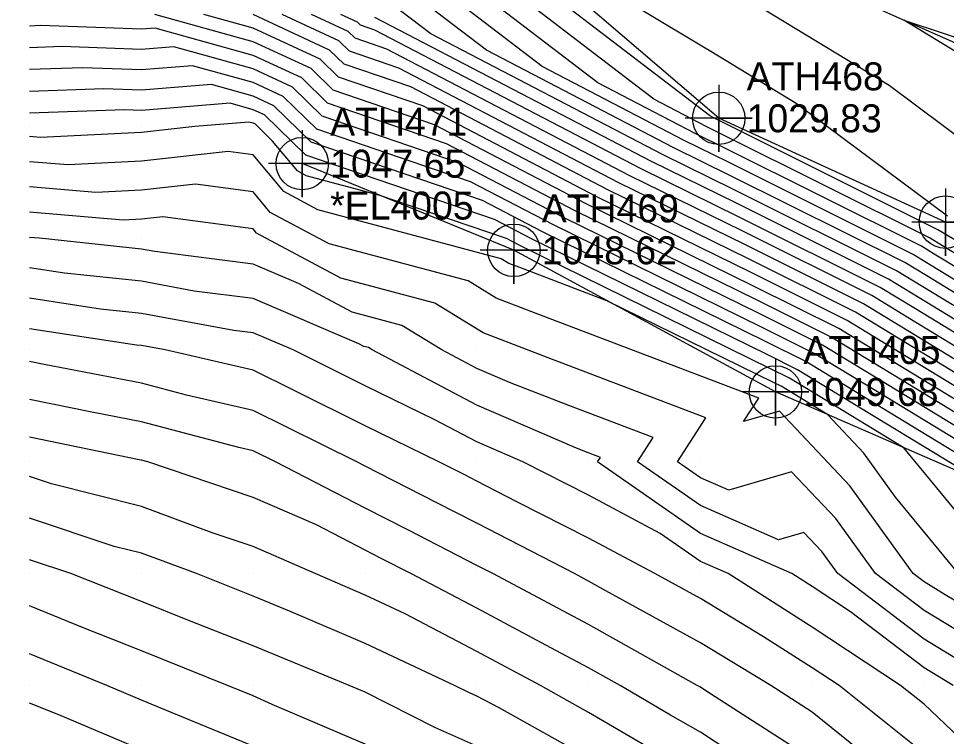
# Model space of a CAD drawing. Extents: x 1213164 to 1213550, y 766120 to 766870.
# Drawn here: x 1213169 to 1213252, y 766335.4 to 766399.6 of the extents above; entities that cross this region are included whole.
import ezdxf

# ---------------------------------------------------------------- set-up
doc = ezdxf.new("R2010")
doc.units = 0
for name, color, linetype in [('Default', 7, 'Continuous'), ('Exist DTM Breakline', 7, 'Continuous'), ('Exist DTM Breakline Cogo Comment', 7, 'Continuous'), ('Exist DTM Breakline Cogo Elevation', 7, 'Continuous'), ('Exist DTM Breakline Cogo Number', 7, 'Continuous'), ('Exist DTM Breakline Cogo Point CELL', 7, 'Continuous'), ('Exist DTM QL2 LIDAR Elevation Point', 7, 'Continuous'), ('Exist Roads EOP', 7, 'Continuous')]:
    doc.layers.add(name, color=color, linetype=linetype)

msp = doc.modelspace()

# ---------------------------------------------------------------- linework, layer by layer
at = {"layer": 'Default'}
for points in [[(1213252.099, 766381.968), (1213238.569, 766392.051), (1213230.917, 766396.699), (1213230.271, 766397.092), (1213210.05, 766409.212)], [(1213302.597, 766358.408), (1213282.153, 766375.636), (1213280.103, 766377.363), (1213253.141, 766379.599), (1213251.598, 766380.538), (1213251.233, 766380.76), (1213231.678, 766390.516), (1213231.474, 766390.617), (1213230.808, 766390.964), (1213207.579, 766408.748)], [(1213300.518, 766357.868), (1213281.492, 766373.902), (1213279.584, 766375.509), (1213254.492, 766377.59), (1213251.259, 766379.558), (1213250.495, 766380.022), (1213231.934, 766389.283), (1213230.499, 766389.988), (1213225.821, 766392.426), (1213206.352, 766407.332)], [(1213304.578, 766352.413), (1213298.807, 766356.947), (1213298.439, 766357.329), (1213280.831, 766372.168), (1213279.065, 766373.656), (1213255.843, 766375.581), (1213250.92, 766378.578), (1213249.758, 766379.285), (1213232.19, 766388.05), (1213229.523, 766389.36), (1213220.835, 766393.889), (1213205.126, 766405.916)], [(1213304.23, 766350.488), (1213296.832, 766356.3), (1213296.361, 766356.79), (1213280.17, 766370.434), (1213278.547, 766371.802), (1213257.194, 766373.572), (1213250.581, 766377.597), (1213249.02, 766378.548), (1213232.445, 766386.817), (1213228.548, 766388.731), (1213215.848, 766395.352), (1213203.899, 766404.5)], [(1213248.618, 766403.962), (1213263.002, 766397.56), (1213276.559, 766386.527), (1213281.848, 766382.566), (1213283.669, 766380.515), (1213285.825, 766378.11), (1213289.231, 766374.252), (1213283.474, 766379.104), (1213281.14, 766381.071), (1213276.351, 766381.468), (1213254.307, 766388.113), (1213246.883, 766393.646), (1213230.055, 766403.868)], [(1213303.882, 766348.563), (1213294.857, 766355.653), (1213294.282, 766356.251), (1213279.509, 766368.7), (1213278.028, 766369.948), (1213258.545, 766371.563), (1213250.242, 766376.617), (1213248.282, 766377.811), (1213232.701, 766385.584), (1213227.572, 766388.103), (1213210.861, 766396.814), (1213202.672, 766403.084)], [(1213303.534, 766346.638), (1213292.883, 766355.006), (1213292.204, 766355.711), (1213278.849, 766366.966), (1213277.51, 766368.094), (1213259.896, 766369.555), (1213249.903, 766375.637), (1213247.544, 766377.073), (1213232.957, 766384.351), (1213226.597, 766387.474), (1213205.874, 766398.277), (1213201.445, 766401.668)], [(1213305.353, 766325.548), (1213297.859, 766333.832), (1213287.001, 766344.237), (1213279.059, 766350.477), (1213277.654, 766351.936), (1213274.223, 766354.827), (1213273.879, 766355.117), (1213269.354, 766355.492), (1213247.531, 766368.776), (1213242.379, 766371.912), (1213234.746, 766375.72), (1213219.769, 766383.075), (1213206.226, 766390.135), (1213197.148, 766393.231), (1213195.169, 766395.169), (1213190, 766397.563), (1213181.204, 766400)], [(1213299.261, 766335.539), (1213291.938, 766342.557), (1213281.033, 766351.124), (1213279.733, 766352.475), (1213274.884, 766356.561), (1213274.398, 766356.971), (1213268.003, 766357.501), (1213247.87, 766369.756), (1213243.117, 766372.649), (1213234.49, 766376.953), (1213220.745, 766383.704), (1213205.157, 766391.829), (1213197.638, 766394.394), (1213195.999, 766395.999), (1213190, 766398.778), (1213185.588, 766400)], [(1213300.664, 766337.246), (1213296.875, 766340.877), (1213283.008, 766351.771), (1213281.811, 766353.015), (1213275.545, 766358.295), (1213274.916, 766358.825), (1213266.652, 766359.51), (1213248.209, 766370.736), (1213243.855, 766373.387), (1213234.235, 766378.186), (1213221.72, 766384.332), (1213204.087, 766393.524), (1213198.128, 766395.556), (1213196.828, 766396.828), (1213190, 766399.992)], [(1213301.812, 766339.197), (1213284.983, 766352.418), (1213283.89, 766353.554), (1213276.205, 766360.029), (1213275.435, 766360.679), (1213265.301, 766361.519), (1213248.548, 766371.716), (1213244.593, 766374.124), (1213233.979, 766379.419), (1213222.695, 766384.961), (1213203.018, 766395.218), (1213198.618, 766396.719), (1213197.658, 766397.658), (1213192.603, 766400)], [(1213302.49, 766340.863), (1213286.958, 766353.065), (1213285.968, 766354.093), (1213276.866, 766361.763), (1213275.954, 766362.533), (1213263.95, 766363.528), (1213248.887, 766372.697), (1213245.33, 766374.861), (1213233.723, 766380.652), (1213223.671, 766385.589), (1213201.949, 766396.913), (1213199.107, 766397.882), (1213198.488, 766398.488), (1213195.224, 766400)], [(1213302.838, 766342.788), (1213288.933, 766353.712), (1213288.047, 766354.633), (1213277.527, 766363.498), (1213276.472, 766364.386), (1213262.599, 766365.537), (1213249.226, 766373.677), (1213246.068, 766375.599), (1213233.468, 766381.885), (1213224.646, 766386.218), (1213200.879, 766398.607), (1213199.597, 766399.044), (1213199.318, 766399.318), (1213197.845, 766400)], [(1213303.186, 766344.713), (1213290.908, 766354.359), (1213290.125, 766355.172), (1213278.188, 766365.232), (1213276.991, 766366.24), (1213261.247, 766367.546), (1213249.565, 766374.657), (1213246.806, 766376.336), (1213233.212, 766383.118), (1213225.622, 766386.846), (1213200.887, 766399.74)], [(1213248.178, 766399.505), (1213255.505, 766397.074), (1213258.06, 766395.937), (1213262.243, 766392.532), (1213256.515, 766394.259), (1213255.196, 766395.241), (1213248.178, 766399.505)], [(1213302.744, 766325.175), (1213296.457, 766332.125), (1213282.064, 766345.917), (1213277.084, 766349.83), (1213275.576, 766351.397), (1213273.562, 766353.093), (1213273.36, 766353.263), (1213270.705, 766353.484), (1213247.193, 766367.796), (1213241.641, 766371.175), (1213235.002, 766374.487), (1213218.794, 766382.447), (1213207.296, 766388.441), (1213196.658, 766392.069), (1213194.339, 766394.339), (1213190, 766396.349), (1213181.218, 766398.782), (1213180, 766398.685), (1213170.991, 766399.009), (1213170, 766398.972)], [(1213300.135, 766324.802), (1213295.055, 766330.418), (1213277.127, 766347.598), (1213275.109, 766349.183), (1213273.497, 766350.858), (1213272.902, 766351.359), (1213272.842, 766351.41), (1213272.057, 766351.475), (1213246.854, 766366.815), (1213240.903, 766370.437), (1213235.257, 766373.254), (1213217.818, 766381.818), (1213208.365, 766386.746), (1213196.168, 766390.906), (1213193.509, 766393.509), (1213190, 766395.135), (1213182.897, 766397.103), (1213180, 766396.872), (1213172.872, 766397.128), (1213170, 766397.021)], [(1213303.716, 766317.22), (1213297.526, 766324.429), (1213293.652, 766328.711), (1213275.153, 766346.438), (1213274.173, 766347.51), (1213273.467, 766348.054), (1213272.271, 766349.201), (1213271.551, 766349.728), (1213270.143, 766350.562), (1213268.666, 766352.352), (1213246.515, 766365.835), (1213240.165, 766369.7), (1213235.513, 766372.021), (1213216.843, 766381.19), (1213209.435, 766385.052), (1213195.678, 766389.743), (1213192.68, 766392.68), (1213190, 766393.921), (1213184.577, 766395.423), (1213180, 766395.058), (1213174.753, 766395.247), (1213170, 766395.07)], [(1213302.619, 766315.088), (1213294.917, 766324.056), (1213292.25, 766327.004), (1213279.514, 766339.209), (1213275.46, 766343.643), (1213272.538, 766345.896), (1213271.662, 766346.735), (1213269.701, 766348.17), (1213265.866, 766350.443), (1213261.842, 766355.319), (1213246.176, 766364.855), (1213239.428, 766368.963), (1213235.769, 766370.788), (1213215.868, 766380.561), (1213210.504, 766383.357), (1213195.188, 766388.581), (1213191.85, 766391.85), (1213190, 766392.707), (1213186.256, 766393.744), (1213180, 766393.245), (1213176.634, 766393.366), (1213170, 766393.119)], [(1213301.521, 766312.955), (1213292.308, 766323.683), (1213290.848, 766325.297), (1213283.875, 766331.98), (1213276.747, 766339.777), (1213271.609, 766343.737), (1213271.054, 766344.269), (1213267.852, 766346.612), (1213261.588, 766350.323), (1213255.019, 766358.286), (1213245.837, 766363.875), (1213238.69, 766368.225), (1213236.024, 766369.555), (1213214.892, 766379.933), (1213211.573, 766381.663), (1213194.698, 766387.418), (1213191.02, 766391.02), (1213190, 766391.492), (1213187.936, 766392.064), (1213180, 766391.432), (1213178.515, 766391.485), (1213170, 766391.167)], [(1213257.311, 766350.204), (1213248.195, 766361.253), (1213245.498, 766362.895), (1213237.952, 766367.488), (1213236.28, 766368.322), (1213213.917, 766379.305), (1213212.643, 766379.969), (1213201.24, 766383.857), (1213194.746, 766385.586), (1213193.951, 766386.012), (1213191.722, 766388.69), (1213190.19, 766390.19), (1213190, 766390.278), (1213189.615, 766390.385), (1213184.785, 766390), (1213180, 766389.457), (1213170.989, 766389.011), (1213170, 766389.094)], [(1213253.033, 766350.085), (1213247.455, 766356.846), (1213244.623, 766360.776), (1213241.371, 766364.22), (1213237.214, 766366.751), (1213236.535, 766367.089), (1213221.632, 766374.408), (1213213.857, 766377.364), (1213212.875, 766377.744), (1213212.189, 766378.163), (1213195.776, 766382.533), (1213192.735, 766384.161), (1213190, 766387.447), (1213187.753, 766387.753), (1213180, 766386.872), (1213173.452, 766386.548), (1213170, 766386.839)], [(1213262.303, 766341.939), (1213251.894, 766348.106), (1213250, 766349.256), (1213249.021, 766350), (1213243.367, 766357.847), (1213237.058, 766364.528), (1213233.859, 766363.593), (1213235.215, 766365.688), (1213215.311, 766373.254), (1213211.724, 766374.643), (1213209.22, 766376.174), (1213196.805, 766379.479), (1213191.518, 766382.31), (1213190, 766384.134), (1213184.837, 766384.837), (1213180, 766384.288), (1213175.914, 766384.086), (1213170, 766384.584)], [(1213258.406, 766341.594), (1213250, 766346.698), (1213245.654, 766350), (1213242.11, 766354.919), (1213238.156, 766359.106), (1213232.537, 766357.463), (1213230, 766358.575), (1213227.959, 766360), (1213230.497, 766363.924), (1213216.765, 766369.145), (1213210.573, 766371.542), (1213206.25, 766374.186), (1213197.834, 766376.426), (1213190.302, 766380.459), (1213190, 766380.821), (1213181.922, 766381.922), (1213180, 766381.704), (1213178.377, 766381.623), (1213170, 766382.329)], [(1213256.819, 766340), (1213250, 766344.141), (1213242.287, 766350), (1213240.854, 766351.99), (1213239.254, 766353.684), (1213236.981, 766353.019), (1213230, 766356.079), (1213224.382, 766360), (1213225.78, 766362.161), (1213218.219, 766365.035), (1213212.909, 766367.091), (1213210, 766368.348), (1213206.872, 766370), (1213203.28, 766372.197), (1213198.863, 766373.372), (1213194.051, 766375.949), (1213190, 766377.684), (1213181.202, 766378.798), (1213180, 766379.02), (1213170.871, 766380), (1213170, 766380.073)], [(1213252.608, 766340), (1213250, 766341.583), (1213243.412, 766346.588), (1213240, 766348.837), (1213238.174, 766350), (1213230, 766353.582), (1213220.806, 766360), (1213221.063, 766360.397), (1213219.672, 766360.926), (1213218.696, 766361.304), (1213210, 766365.062), (1213200.65, 766370), (1213200.31, 766370.208), (1213199.892, 766370.319), (1213199.437, 766370.563), (1213190, 766374.604), (1213184.728, 766375.272), (1213180, 766376.143), (1213173.118, 766376.882), (1213170, 766377.356)], [(1213288.488, 766300), (1213280, 766308.773), (1213278.784, 766310), (1213270, 766319.601), (1213269.614, 766320), (1213260, 766328.926), (1213258.753, 766330), (1213250, 766338.319), (1213247.903, 766340), (1213240, 766345.208), (1213232.477, 766350), (1213230, 766351.086), (1213226.405, 766353.595), (1213220, 766357.02), (1213214.108, 766360), (1213210, 766361.775), (1213206.237, 766363.763), (1213200, 766366.795), (1213193.559, 766370), (1213190, 766371.524), (1213188.255, 766371.745), (1213180, 766373.266), (1213176.341, 766373.659), (1213170, 766374.624)], [(1213254.11, 766330), (1213250, 766333.906), (1213242.397, 766340), (1213240, 766341.58), (1213235.649, 766344.351), (1213230, 766347.761), (1213225.936, 766350), (1213220, 766353.174), (1213213.578, 766356.422), (1213210, 766358.269), (1213208.856, 766358.856), (1213206.616, 766360), (1213200, 766363.217), (1213193.598, 766366.402), (1213190, 766368.183), (1213182.11, 766370), (1213180, 766370.389), (1213179.565, 766370.435), (1213170, 766371.892)], [(1213280, 766300.545), (1213270.63, 766310), (1213270, 766310.688), (1213260.995, 766320), (1213260, 766320.923), (1213253.326, 766326.674), (1213250, 766329.544), (1213249.402, 766330), (1213240, 766337.619), (1213236.293, 766340), (1213230, 766343.799), (1213221.541, 766348.459), (1213220, 766349.323), (1213218.726, 766350), (1213210, 766354.505), (1213206.367, 766356.367), (1213200, 766359.619), (1213199.265, 766360), (1213190, 766364.587), (1213184.041, 766365.959), (1213180, 766367.027), (1213171.308, 766368.692), (1213170, 766368.959)], [(1213276.631, 766300), (1213270, 766306.688), (1213266.673, 766310), (1213260, 766316.88), (1213256.467, 766320), (1213250, 766325.581), (1213244.199, 766330), (1213240, 766333.403), (1213230.486, 766339.514), (1213230, 766339.835), (1213229.895, 766339.895), (1213229.716, 766340), (1213220, 766345.451), (1213211.434, 766350), (1213210, 766350.74), (1213203.878, 766353.878), (1213200, 766355.859), (1213191.999, 766360), (1213190, 766360.99), (1213188.714, 766361.286), (1213180, 766363.589), (1213175.561, 766364.439), (1213170, 766365.577)], [(1213270, 766302.77), (1213262.739, 766310), (1213260, 766312.824), (1213251.874, 766320), (1213250, 766321.617), (1213243.209, 766326.791), (1213240, 766329.186), (1213238.829, 766330), (1213230, 766335.826), (1213227.335, 766337.335), (1213222.813, 766340), (1213220, 766341.578), (1213216.634, 766343.366), (1213210, 766346.896), (1213204.099, 766350), (1213201.389, 766351.389), (1213200, 766352.098), (1213195.651, 766354.349), (1213190, 766356.816), (1213180.571, 766360), (1213180, 766360.151), (1213179.813, 766360.187), (1213170, 766362.194)], [(1213268.891, 766300), (1213260, 766308.854), (1213258.598, 766310), (1213250, 766317.59), (1213246.649, 766320), (1213240, 766324.962), (1213232.752, 766330), (1213230, 766331.816), (1213224.775, 766334.775), (1213220, 766337.59), (1213215.698, 766340), (1213210, 766343.032), (1213203.604, 766346.396), (1213200, 766348.087), (1213195.55, 766350), (1213190, 766352.422), (1213186.342, 766353.658), (1213180, 766356.001), (1213171.968, 766358.032), (1213170, 766358.69)], [(1213265.104, 766300), (1213260, 766305.082), (1213253.986, 766310), (1213250, 766313.518), (1213240.988, 766320), (1213240, 766320.738), (1213237.58, 766322.42), (1213230, 766327.738), (1213226.127, 766330), (1213222.215, 766332.215), (1213220, 766333.521), (1213211.993, 766338.007), (1213210, 766339.037), (1213209.334, 766339.334), (1213208.013, 766340), (1213200, 766343.759), (1213193.406, 766346.594), (1213190, 766347.998), (1213184.923, 766350), (1213180, 766351.819), (1213177.565, 766352.435), (1213170, 766354.961)], [(1213260, 766301.311), (1213252.811, 766307.189), (1213250, 766309.475), (1213249.199, 766310), (1213240, 766316.542), (1213235.135, 766320), (1213230, 766323.602), (1213221.338, 766328.662), (1213220, 766329.432), (1213218.836, 766330), (1213210, 766334.564), (1213206.242, 766336.242), (1213200, 766339.388), (1213198.575, 766340), (1213190, 766343.534), (1213184.165, 766345.835), (1213180, 766347.509), (1213173.693, 766350), (1213170, 766351.233)], [(1213256.902, 766300), (1213250, 766305.613), (1213243.308, 766310), (1213240, 766312.352), (1213231.867, 766318.133), (1213230, 766319.462), (1213229.055, 766320), (1213220, 766325.211), (1213210.178, 766330), (1213210, 766330.092), (1213203.15, 766333.15), (1213200, 766334.738), (1213191.698, 766338.302), (1213190, 766339.065), (1213187.713, 766340), (1213180, 766343.099), (1213174.877, 766345.123), (1213170, 766347.129)], [(1213250, 766301.751), (1213244.916, 766305.084), (1213240, 766308.217), (1213237.431, 766310), (1213230, 766315.291), (1213221.721, 766320), (1213220, 766320.99), (1213218.068, 766321.932), (1213210, 766325.834), (1213200.188, 766330), (1213200.058, 766330.058), (1213200, 766330.087), (1213199.847, 766330.153), (1213190, 766334.579), (1213182.255, 766337.745), (1213180, 766338.678), (1213176.902, 766340), (1213170, 766342.839)], [(1213246.514, 766300), (1213240, 766304.152), (1213231.573, 766310), (1213230, 766311.12), (1213227.402, 766312.598), (1213220, 766316.876), (1213213.267, 766320), (1213210, 766321.58), (1213207.254, 766322.746), (1213200, 766325.921), (1213190.206, 766330), (1213190, 766330.092), (1213189.844, 766330.156), (1213180, 766334.227), (1213172.625, 766337.375), (1213170, 766338.401)]]:
    msp.add_lwpolyline(points, dxfattribs=at)
at = {"layer": 'Exist DTM Breakline'}
for points in [[(1213422.776, 766171.254), (1213409.831, 766196.926), (1213386.657, 766233.346), (1213364.326, 766270.025), (1213348.91, 766295.975), (1213348.91, 766295.975), (1213325.275, 766332.542), (1213305.812, 766359.242), (1213281.253, 766381.475), (1213256.992, 766395.586), (1213227.813, 766408.558), (1213197.433, 766416.071)], [(1213251.907, 766381.433), (1213231.636, 766390.721), (1213205.16, 766413.401)], [(1213289.151, 766323.232), (1213272.624, 766350.631), (1213236.71, 766366.247), (1213213.309, 766378.913), (1213194.382, 766386.667)]]:
    msp.add_lwpolyline(points, dxfattribs=at)
at = {"layer": 'Exist DTM Breakline Cogo Point CELL'}
for points in [[(1213231.636, 766393.721), (1213231.636, 766387.721), (1213231.636, 766390.721), (1213234.636, 766390.721), (1213228.636, 766390.721)], [(1213194.382, 766389.667), (1213194.382, 766383.667), (1213194.382, 766386.667), (1213197.382, 766386.667), (1213191.382, 766386.667)], [(1213251.907, 766384.433), (1213251.907, 766378.433), (1213251.907, 766381.433), (1213254.907, 766381.433), (1213248.907, 766381.433)], [(1213213.309, 766381.913), (1213213.309, 766375.913), (1213213.309, 766378.913), (1213216.309, 766378.913), (1213210.309, 766378.913)], [(1213236.71, 766369.247), (1213236.71, 766363.247), (1213236.71, 766366.247), (1213239.71, 766366.247), (1213233.71, 766366.247)]]:
    msp.add_lwpolyline(points, dxfattribs=at)
for centre in [(1213231.636, 766390.721), (1213194.382, 766386.667), (1213251.907, 766381.433), (1213213.309, 766378.913), (1213236.71, 766366.247)]:
    msp.add_circle(centre, 2.344, dxfattribs=at)
at = {"layer": 'Exist DTM QL2 LIDAR Elevation Point'}
for p, q in [((1213170, 766390), (1213170, 766390)), ((1213180, 766390), (1213180, 766390)), ((1213190, 766390), (1213190, 766390)), ((1213170, 766380), (1213170, 766380)), ((1213180, 766380), (1213180, 766380)), ((1213190, 766380), (1213190, 766380)), ((1213170, 766370), (1213170, 766370)), ((1213180, 766370), (1213180, 766370)), ((1213190, 766370), (1213190, 766370)), ((1213200, 766370), (1213200, 766370)), ((1213210, 766370), (1213210, 766370)), ((1213170, 766360), (1213170, 766360)), ((1213180, 766360), (1213180, 766360)), ((1213190, 766360), (1213190, 766360)), ((1213200, 766360), (1213200, 766360)), ((1213210, 766360), (1213210, 766360)), ((1213220, 766360), (1213220, 766360)), ((1213230, 766360), (1213230, 766360)), ((1213170, 766350), (1213170, 766350)), ((1213180, 766350), (1213180, 766350)), ((1213190, 766350), (1213190, 766350)), ((1213200, 766350), (1213200, 766350)), ((1213210, 766350), (1213210, 766350)), ((1213220, 766350), (1213220, 766350)), ((1213230, 766350), (1213230, 766350)), ((1213240, 766350), (1213240, 766350)), ((1213250, 766350), (1213250, 766350)), ((1213170, 766340), (1213170, 766340)), ((1213180, 766340), (1213180, 766340)), ((1213190, 766340), (1213190, 766340)), ((1213200, 766340), (1213200, 766340)), ((1213210, 766340), (1213210, 766340)), ((1213220, 766340), (1213220, 766340)), ((1213230, 766340), (1213230, 766340)), ((1213240, 766340), (1213240, 766340)), ((1213250, 766340), (1213250, 766340))]:
    msp.add_line(p, q, dxfattribs=at)
at = {"layer": 'Exist Roads EOP'}
msp.add_spline([(1213169.012, 766424.202), (1213197.361, 766422.679), (1213222.732, 766418.674), (1213259.828, 766408.159), (1213283.389, 766394.331), (1213303.908, 766375.84), (1213322.371, 766351.308)], degree=3, dxfattribs=at)

# ---------------------------------------------------------------- texts
at = {"layer": 'Exist DTM Breakline Cogo Comment'}
msp.add_text('*EL4005', height=2.5, dxfattribs=at).set_placement((1213196.882, 766381.667))
at = {"layer": 'Exist DTM Breakline Cogo Elevation'}
for s, p in [('1029.83', (1213234.136, 766389.471)), ('1047.65', (1213196.882, 766385.417)), ('1048.62', (1213215.809, 766377.663)), ('1049.68', (1213239.21, 766364.997))]:
    msp.add_text(s, height=2.5, dxfattribs=at).set_placement(p)
at = {"layer": 'Exist DTM Breakline Cogo Number'}
for s, p in [('ATH468', (1213234.136, 766393.221)), ('ATH471', (1213196.882, 766389.167)), ('ATH469', (1213215.809, 766381.413)), ('ATH405', (1213239.21, 766368.747))]:
    msp.add_text(s, height=2.5, dxfattribs=at).set_placement(p)

doc.saveas('drawing.dxf')
